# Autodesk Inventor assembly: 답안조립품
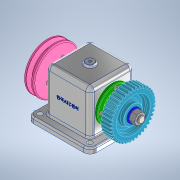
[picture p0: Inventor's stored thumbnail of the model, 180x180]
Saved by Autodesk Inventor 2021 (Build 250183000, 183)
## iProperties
Created: 2022-07
Part Number: 답안조립품
Document SubType Name: Assembly
Designer: j
Author: j
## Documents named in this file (12)
- C:\Users\j\Desktop\720706V1002\답안조립품.iam
- C:\Users\j\Desktop\720706V1002\본체.ipt
- C:\Users\j\Desktop\720706V1002\V벨트풀리.ipt
- C:\Users\j\Desktop\720706V1002\너트 M12x1.25.ipt
- C:\Users\j\Desktop\720706V1002\베어링 6204.ipt
- C:\Users\j\Desktop\720706V1002\볼트 M4x0.7.ipt
- C:\Users\j\Desktop\720706V1002\스퍼기어.ipt
- C:\Users\j\Desktop\720706V1002\오일실 20x35x8.ipt
- C:\Users\j\Desktop\720706V1002\와셔 12x24.ipt
- C:\Users\j\Desktop\720706V1002\축.ipt
- C:\Users\j\Desktop\720706V1002\커버.ipt
- C:\Users\j\Desktop\720706V1002\키 5x5.ipt
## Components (1 placed, 1 different names)
1. V벨트풀리:1
## Named parameters: d12_d5 = 0, d13_d6 = 0
